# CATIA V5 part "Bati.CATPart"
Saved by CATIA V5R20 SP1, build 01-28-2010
Part number: Bati
Bounding box of the stored display mesh (mm): x -70 to 70, y -8 to 60, z 0 to 54.844
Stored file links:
  E:\EDELI\gcausse\Edeli_2012_686_gcausse\Bati.CATPart
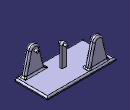
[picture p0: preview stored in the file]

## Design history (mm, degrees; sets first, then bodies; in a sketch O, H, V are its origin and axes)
Body1 (main body)
  Sketch1 on xy-plane, origin (0, 0, 0), H (1, 0, 0), V (0, 1, 0)
    line L1 (-70, 60) -> (70, 60)
    line L2 (70, 60) -> (70, -20)
    line L3 (70, -20) -> (-70, -20)
    line L4 (-70, -20) -> (-70, 60)
    distance L1 L3 = 80
    distance L3 H = 20
    horizontal: L1 H, L3 H
    vertical: L2 V, L4 V
  Pad1: profile Sketch1, direction (0, 0, 1), length 5
  Sketch2 on end face of Pad1, origin (0, 0, 5), H (1, 0, 0), V (0, 1, 0)
    line L1 (-60, 5) -> (60, 5)
    line L2 (60, 5) -> (60, -5)
    line L3 (60, -5) -> (-60, -5)
    line L4 (-60, -5) -> (-60, 5)
    reference projected line E1 (70, 60) -> (-70, 60) from edge [face of Pad1 from Sketch1.L1 | end face of Pad1]
    distance L1 E1 = 55
    distance L3 L1 = 10
    horizontal: L1 H, L3 H
    vertical: L2 V, L4 V
  Pad2: profile Sketch2, direction (0, 0, 1), length 60
  Sketch3 on face of Pad2 from Sketch2.L1, origin (0, 5, 0), H (-1, 0, 0), V (0, 0, 1)
    point P1 (-60, 5)
    line L1 (-60, 5) -> (-49.7178, 47.3589)
    arc A1 centre (-40, 45) radius 10 from (-49.7178, 47.3589) to (-30.3407, 47.5882) cw
    point P3 (-40, 45)
    line L2 (-30.3407, 47.5882) -> (-25, 27.6563)
    point P5 (-25, 27.6563)
    point P6 (25, 27.6563)
    point P7 (40, 45)
    line L3 (60, 5) -> (60, 99.8515)
    line L4 (60, 99.8515) -> (-60, 99.8515)
    line L5 (-60, 99.8515) -> (-60, 5)
    reference projected line E1 (60, 5) -> (60, 65) from edge [face of Pad2 from Sketch2.L4 | face of Pad2 from Sketch2.L1]
    reference projected line E2 (-60, 65) -> (60, 65) from edge [face of Pad2 from Sketch2.L1 | end face of Pad2]
    reference projected line E3 (-60, 65) -> (60, 65) from edge [face of Pad2 from Sketch2.L1 | end face of Pad2]
    reference projected line E4 (-60, 5) -> (-60, 65) from edge [face of Pad2 from Sketch2.L1 | face of Pad2 from Sketch2.L2]
    line L6 (-25, 27.6563) -> (-18.9293, 5)
    line L7 (-18.9293, 5) -> (60, 5)
    reference projected line E5 (-60, 5) -> (60, 5) from edge [end face of Pad1 | face of Pad2 from Sketch2.L1]
    reference projected line E6 (-60, 5) -> (60, 5) from edge [end face of Pad1 | face of Pad2 from Sketch2.L1]
    distance P5 L5 = 35
    distance P3 E2 = 20
    distance P7 E3 = 20
    radius A1 = 10
    distance P3 P7 = 80
    distance E5 P1 = 0
    distance L7 E6 = 0
    tangency: A1 L1, L2 A1, L6 A1
    vertical: L3 V, L5 V
    horizontal: L4 H, L7 H
    coincidence: E1 L3, L5 E4
  Pocket1: profile Sketch3, direction (0, -1, 0), length 10
  Sketch4 on face of Pad1, origin (0, 0, 5), H (1, 0, 0), V (0, 1, 0)
    line L1 (-60, 55) -> (-20, 55)
    line L2 (-20, 55) -> (-20, 45)
    line L3 (-20, 45) -> (-60, 45)
    line L4 (-60, 45) -> (-60, 55)
    reference projected line E1 (70, 60) -> (-70, 60) from edge [face of Pad1 from Sketch1.L1 | end face of Pad1]
    distance L3 E1 = 15
    horizontal: L1 H, L3 H
    vertical: L2 V, L4 V
  Pad3: profile Sketch4, direction (0, 0, 1), length 60
  Sketch5 on face of Pad3 from Sketch4.L3, origin (0, 45, 0), H (1, 0, 0), V (0, 0, 1)
    point P1 (-60, 5)
    line L1 (-60, 5) -> (-49.7178, 47.3589)
    arc A1 centre (-40, 45) radius 10 from (-49.7178, 47.3589) to (-30.2822, 47.3589) cw
    point P3 (-40, 45)
    line L2 (-30.2822, 47.3589) -> (-20, 5)
    point P5 (-20, 5)
    line L3 (-20, 5) -> (-20, 75)
    line L4 (-20, 75) -> (-60, 75)
    line L5 (-60, 75) -> (-60, 5)
    reference projected line E1 (-60, 5) -> (-20, 5) from edge [face of Pad1 | face of Pad3 from Sketch4.L3]
    reference projected point E2 (-20, 5) from vertex [face of Pad3 from Sketch4.L2 | face of Pad1 | face of Pad3 from Sketch4.L3]
    reference projected point E3 (-60, 5) from vertex [face of Pad3 from Sketch4.L3 | face of Pad1 | face of Pad3 from Sketch4.L4]
    radius A1 = 10
    distance P3 E1 = 40
    tangency: A1 L1, L2 A1
    vertical: L3 V, L5 V
    horizontal: L4 H
    coincidence: P5 E2, P1 E3
    equidistance: L3 L5 P3
  Pocket2: profile Sketch5, direction (0, 1, 0), length 60
  Fillet1: radius 3, on face of Pocket2 from Sketch5.L1
  Fillet2: radius 3, on edge [face of Pocket1 | face of Pad2 from Sketch2.L3]
  Fillet3: radius 3, on face of Pocket1
  Fillet4: radius 3, on edge [face of Pad2 from Sketch2.L1 | face of Pocket1 from Sketch3.L1]
  Sketch6 on face of Pad3 from Sketch4.L3, origin (0, 45, 0), H (1, 0, 0), V (0, 0, 1)
    circle A1 centre (-40, 45) radius 2.5
    reference projected point E1 (-40, 45) from axis of face of Pocket2 from Sketch5.A1
    radius A1 = 2.5
    concentricity: A1 E1
  Pad4: profile Sketch6, direction (0, -1, 0), length 5
  Sketch7 on face of Pocket1, origin (0, 0, 5), H (1, 0, 0), V (0, 1, 0)
    line L1 (-5, 25) -> (5, 25)
    line L2 (5, 25) -> (5, 20)
    line L3 (5, 20) -> (-5, 20)
    line L4 (-5, 20) -> (-5, 25)
    reference projected line E1 (-70, -20) -> (70, -20) from edge [face of Pad1 from Sketch1.L3 | face of Fillet3]
    reference projected line E2 (70, -20) -> (70, 60) from edge [face of Pad1 from Sketch1.L2 | face of Fillet3]
    distance L1 L3 = 5
    distance L3 E1 = 40
    distance L4 L2 = 10
    distance L2 E2 = 65
    horizontal: L1 H, L3 H
    vertical: L2 V, L4 V
  Pad5: profile Sketch7, direction (0, 0, 1), length 50
  Sketch8 on face of Pad5 from Sketch7.L1, origin (0, 25, 0), H (-1, 0, 0), V (0, 0, 1)
    point P1 (-5, 5)
    line L1 (-5, 5) -> (-5, 45)
    arc A1 centre (0, 45) radius 5 from (-5, 45) to (5, 45) cw
    point P3 (0, 45)
    line L2 (5, 45) -> (5, 5)
    point P5 (5, 5)
    line L3 (5, 5) -> (5, 65)
    line L4 (5, 65) -> (-5, 65)
    point P7 (-5, 65)
    line L5 (-5, 65) -> (-5, 5)
    reference projected point E1 (-5, 5) from vertex [face of Pad5 from Sketch7.L2 | face of Pocket1 | face of Pad5 from Sketch7.L1]
    reference projected point E2 (5, 5) from vertex [face of Pad5 from Sketch7.L1 | face of Pocket1 | face of Pad5 from Sketch7.L4]
    reference projected line E3 (-5, 5) -> (5, 5) from edge [face of Pocket1 | face of Pad5 from Sketch7.L1]
    distance P3 E3 = 40
    vertical: L1 V, L5 V
    tangency: A1 L1, L2 A1, L3 A1
    coincidence: P7 L1, P1 E1, P5 E2
    horizontal: L4 H
  Pocket3: profile Sketch8, direction (0, -1, 0), length 50
  Sketch9 on face of Pad5 from Sketch7.L1, origin (0, 25, 0), H (-1, 0, 0), V (0, 0, 1)
    circle A1 centre (0, 45) radius 2.5
    reference projected arc E1 centre (0, 45) radius 5 from (5, 45) to (-5, 45) ccw from edge [face of Pad5 from Sketch7.L1 | face of Pocket3 from Sketch8.A1]
    reference projected arc E2 centre (0, 45) radius 5 from (5, 45) to (-5, 45) ccw from edge [face of Pad5 from Sketch7.L1 | face of Pocket3 from Sketch8.A1]
    radius A1 = 2.5
    radius E2 = 5 (reference)
    concentricity: A1 E1
  Pad6: profile Sketch9, direction (0, 1, 0), length 5, opposite side length 10
  DatumCurve1
  Sketch10 on face of Pad2 from Sketch2.L1, origin (0, 5, 0), H (-1, 0, 0), V (0, 0, 1)
    circle A1 centre (-40, 45) radius 2.5
    reference projected arc E1 centre (-40, 45) radius 7 from (-33.5888, 42.1899) to (-42.9404, 38.6475) ccw from edge of DatumCurve1
    reference projected arc E2 centre (-40, 45) radius 7 from (-33.5888, 42.1899) to (-42.9404, 38.6475) ccw from edge of DatumCurve1
    radius A1 = 2.5
    radius E2 = 7 (reference)
    concentricity: A1 E1
  Pad7: profile Sketch10, direction (0, 1, 0), length 5
  Sketch11 on face of Pocket1, origin (0, 0, 5), H (1, 0, 0), V (0, 1, 0)
    line L1 (-100, -8) -> (100, -8)
    line L2 (100, -8) -> (100, -28)
    line L3 (100, -28) -> (-100, -28)
    line L4 (-100, -28) -> (-100, -8)
    reference projected line E1 (56.1847, -8) -> (22.8389, -8) from edge [face of Fillet3 | face of Pocket1]
    horizontal: L1 H, L3 H
    vertical: L2 V, L4 V
    coincidence: L1 E1
  Pocket4: profile Sketch11, direction (0, 0, -1), length 5
  Fillet5: radius 3, on edge [face of Pocket1 | face of Pocket4 from Sketch11.L1] (x2); edge [face of Fillet3 | face of Pocket4 from Sketch11.L1]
